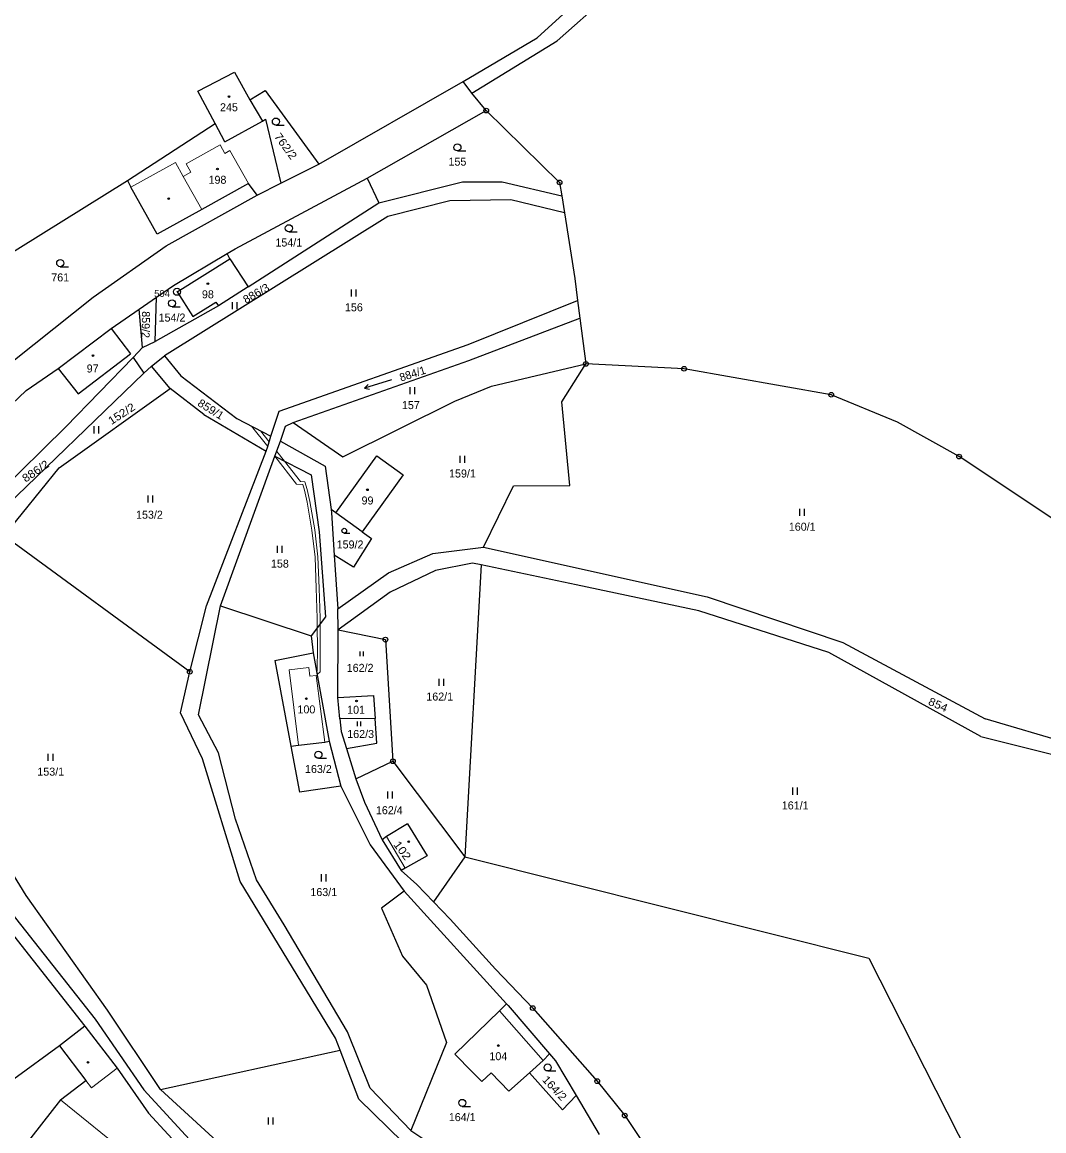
# Model space of a CAD drawing. Extents: x -739410 to -735662, y -942282 to -940043.
# Drawn here: x -737671 to -737454.1, y -940728 to -940492.6 of the extents above; entities that cross this region are included whole.
import ezdxf
from ezdxf.enums import TextEntityAlignment as Align

# ---------------------------------------------------------------- set-up
doc = ezdxf.new("R2010")
doc.units = 0
doc.header["$LTSCALE"] = 0.68
for name, color, linetype, lineweight in [('1', 7, 'Continuous', 25), ('13', 7, 'Continuous', 13), ('3', 7, 'Continuous', 25), ('4', 7, 'Continuous', 13), ('5', 7, 'Continuous', 25), ('8', 7, 'Continuous', 25)]:
    doc.layers.add(name, color=color, linetype=linetype, lineweight=lineweight)
doc.layers.add('2', color=7, linetype='Continuous')

msp = doc.modelspace()

# ---------------------------------------------------------------- linework, layer by layer
at = {"layer": '1'}
for p, q in [((-737561.67, -940495.92), (-737548.71, -940484.07)), ((-737557.45, -940496.56), (-737545.62, -940486.1)), ((-737577.41, -940505.16), (-737561.67, -940495.92)), ((-737575.54, -940507.67), (-737557.45, -940496.56)), ((-737633.69, -940507.25), (-737625.96, -940503.21)), ((-737625.96, -940503.21), (-737622.67, -940509.06)), ((-737608.04, -940522.72), (-737577.41, -940505.16)), ((-737575.54, -940507.67), (-737577.41, -940505.16)), ((-737630.02, -940514.12), (-737633.69, -940507.25)), ((-737622.67, -940509.06), (-737619.45, -940507.08)), ((-737619.45, -940507.08), (-737608.04, -940522.72)), ((-737572.48, -940511.35), (-737575.54, -940507.67)), ((-737622.67, -940509.06), (-737619.97, -940513.57)), ((-737597.76, -940525.71), (-737572.48, -940511.35)), ((-737556.9, -940526.6), (-737572.48, -940511.35)), ((-737648.64, -940526.17), (-737630.02, -940514.12)), ((-737627.97, -940517.97), (-737630.02, -940514.12)), ((-737627.97, -940517.97), (-737619.97, -940513.57)), ((-737619.97, -940513.57), (-737619.32, -940513.15)), ((-737619.32, -940513.15), (-737616.07, -940526.8)), ((-737616.07, -940526.8), (-737608.04, -940522.72)), ((-737686.19, -940549.57), (-737648.64, -940526.17)), ((-737648.64, -940526.17), (-737647.91, -940527.59)), ((-737622.97, -940526.85), (-737632.9, -940532.37)), ((-737625.76, -940540.71), (-737597.76, -940525.71)), ((-737621.09, -940529.34), (-737622.97, -940526.85)), ((-737621.09, -940529.34), (-737616.07, -940526.8)), ((-737597.76, -940525.71), (-737595.26, -940530.94)), ((-737595.26, -940530.94), (-737577.52, -940526.46)), ((-737577.52, -940526.46), (-737569.13, -940526.46)), ((-737569.13, -940526.46), (-737556.45, -940529.45)), ((-737556.9, -940526.6), (-737556.45, -940529.45)), ((-737642.33, -940537.57), (-737647.91, -940527.59)), ((-737640.41, -940540.09), (-737621.09, -940529.34)), ((-737623.02, -940548.79), (-737595.26, -940530.94)), ((-737580.24, -940530.51), (-737593.38, -940533.82)), ((-737567.25, -940530.31), (-737580.24, -940530.51)), ((-737555.89, -940533.03), (-737567.25, -940530.31)), ((-737556.45, -940529.45), (-737555.89, -940533.03)), ((-737632.9, -940532.37), (-737642.33, -940537.57)), ((-737593.38, -940533.82), (-737640.78, -940563.44)), ((-737555.89, -940533.03), (-737553.7, -940547)), ((-737655.92, -940550.97), (-737640.41, -940540.09)), ((-737627.47, -940541.72), (-737625.76, -940540.71)), ((-737638.91, -940548.51), (-737627.47, -940541.72)), ((-737638.12, -940549.83), (-737626.91, -940542.82)), ((-737626.91, -940542.82), (-737627.47, -940541.72)), ((-737626.91, -940542.82), (-737623.02, -940548.79)), ((-737553.7, -940547), (-737553.08, -940551.7)), ((-737642.46, -940550.97), (-737638.91, -940548.51)), ((-737638.12, -940549.83), (-737634.81, -940555.08)), ((-737623.02, -940548.79), (-737629.35, -940552.84)), ((-737672.65, -940564.31), (-737655.92, -940550.97)), ((-737646.16, -940553.54), (-737642.46, -940550.97)), ((-737642.79, -940560.38), (-737642.46, -940550.97)), ((-737629.35, -940552.84), (-737642.79, -940560.38)), ((-737634.81, -940555.08), (-737629.89, -940552.01)), ((-737629.89, -940552.01), (-737629.35, -940552.84)), ((-737576.32, -940561.02), (-737553.08, -940551.7)), ((-737553.08, -940551.7), (-737552.59, -940555.42)), ((-737652.11, -940557.66), (-737646.16, -940553.54)), ((-737645.46, -940561.66), (-737646.16, -940553.54)), ((-737576.17, -940564.43), (-737552.59, -940555.42)), ((-737552.59, -940555.42), (-737551.3, -940565.14)), ((-737663.34, -940566.12), (-737652.11, -940557.66)), ((-737652.11, -940557.66), (-737648, -940563.03)), ((-737647.45, -940563.79), (-737645.46, -940561.66)), ((-737645.46, -940561.66), (-737642.79, -940560.38)), ((-737616.45, -940575.19), (-737576.32, -940561.02)), ((-737661.75, -940578.53), (-737647.45, -940563.79)), ((-737659.16, -940571.5), (-737648, -940563.03)), ((-737647.45, -940563.79), (-737645.19, -940567.1)), ((-737643.53, -940565.59), (-737640.78, -940563.44)), ((-737640.78, -940563.44), (-737637.36, -940567.7)), ((-737613.5, -940577.58), (-737576.17, -940564.43)), ((-737670.2, -940570.81), (-737663.34, -940566.12)), ((-737663.34, -940566.12), (-737659.16, -940571.5)), ((-737643.53, -940565.59), (-737645.19, -940567.1)), ((-737639.58, -940570.36), (-737643.53, -940565.59)), ((-737571.36, -940569.87), (-737551.3, -940565.14)), ((-737556.45, -940573.22), (-737551.3, -940565.14)), ((-737530.47, -940566.17), (-737551.3, -940565.14)), ((-737499.22, -940571.7), (-737530.47, -940566.17)), ((-737645.19, -940567.1), (-737678.21, -940598.98)), ((-737637.36, -940567.7), (-737625.45, -940576.74)), ((-737689.83, -940589.57), (-737670.2, -940570.81)), ((-737663.18, -940587.21), (-737639.58, -940570.36)), ((-737632.47, -940575.86), (-737639.58, -940570.36)), ((-737579.18, -940573.03), (-737571.36, -940569.87)), ((-737485.14, -940577.53), (-737499.22, -940571.7)), ((-737602.91, -940584.85), (-737579.18, -940573.03)), ((-737554.76, -940590.93), (-737556.45, -940573.22)), ((-737632.47, -940575.86), (-737619.22, -940583.69)), ((-737618.23, -940580.49), (-737616.45, -940575.19)), ((-737679.94, -940596.35), (-737661.75, -940578.53)), ((-737625.45, -940576.74), (-737618.23, -940580.49)), ((-737616.16, -940581.55), (-737615.1, -940578.35)), ((-737615.1, -940578.35), (-737613.5, -940577.58)), ((-737613.5, -940577.58), (-737602.91, -940584.85)), ((-737472.09, -940584.82), (-737485.14, -940577.53)), ((-737618.83, -940582.69), (-737618.23, -940580.49)), ((-737619.22, -940583.69), (-737618.83, -940582.69)), ((-737617.35, -940584.76), (-737616.16, -940581.55)), ((-737616.16, -940581.55), (-737606.67, -940586.85)), ((-737631.88, -940616.55), (-737619.22, -940583.69)), ((-737628.92, -940616.53), (-737617.35, -940584.76)), ((-737617.35, -940584.76), (-737609.62, -940588.73)), ((-737604.42, -940596.8), (-737595.72, -940584.68)), ((-737595.72, -940584.68), (-737590.11, -940588.71)), ((-737454.28, -940596.64), (-737472.09, -940584.82)), ((-737674.87, -940601.62), (-737663.18, -940587.21)), ((-737606.67, -940586.85), (-737605.42, -940596.03)), ((-737609.62, -940588.73), (-737607.99, -940600.78)), ((-737590.11, -940588.71), (-737598.8, -940600.79)), ((-737573.07, -940604.08), (-737566.69, -940591)), ((-737566.69, -940591), (-737554.76, -940590.93)), ((-737604.42, -940596.8), (-737605.42, -940596.03)), ((-737605.42, -940596.03), (-737605.32, -940596.76)), ((-737605.32, -940596.76), (-737604.76, -940605.77)), ((-737598.8, -940600.79), (-737604.42, -940596.8)), ((-737433.14, -940611.23), (-737454.28, -940596.64)), ((-737635.43, -940630.52), (-737674.87, -940601.62)), ((-737607.99, -940600.78), (-737606.64, -940618.85)), ((-737596.81, -940602.23), (-737600.68, -940608.28)), ((-737598.8, -940600.79), (-737596.81, -940602.23)), ((-737583.79, -940605.43), (-737573.07, -940604.08)), ((-737573.07, -940604.08), (-737525.58, -940614.62)), ((-737604.76, -940605.77), (-737604, -940617.14)), ((-737600.68, -940608.28), (-737604.76, -940605.77)), ((-737593.2, -940609.54), (-737583.79, -940605.43)), ((-737583.22, -940609.03), (-737592.89, -940613.59)), ((-737575.39, -940607.43), (-737583.22, -940609.03)), ((-737573.54, -940607.82), (-737577.04, -940669.84)), ((-737573.54, -940607.82), (-737575.39, -940607.43)), ((-737553.37, -940612.07), (-737573.54, -940607.82)), ((-737604, -940617.14), (-737593.2, -940609.54)), ((-737592.89, -940613.59), (-737603.92, -940621.58)), ((-737527.36, -940617.57), (-737553.37, -940612.07)), ((-737525.58, -940614.62), (-737496.8, -940624.3)), ((-737635.43, -940630.52), (-737631.88, -940616.55)), ((-737633.58, -940639.69), (-737628.92, -940616.53)), ((-737628.92, -940616.53), (-737609.62, -940622.86)), ((-737603.92, -940621.58), (-737604, -940617.14)), ((-737499.75, -940626.43), (-737527.36, -940617.57)), ((-737606.64, -940618.85), (-737609.62, -940622.86)), ((-737609.62, -940622.86), (-737609.26, -940626.5)), ((-737603.97, -940636), (-737603.92, -940621.58)), ((-737496.8, -940624.3), (-737466.56, -940640.53)), ((-737617.38, -940628.15), (-737609.26, -940626.5)), ((-737617.38, -940628.15), (-737613.98, -940646.3)), ((-737609.26, -940626.5), (-737605.83, -940645.25)), ((-737467.44, -940644.28), (-737499.75, -940626.43)), ((-737637.39, -940639.21), (-737635.43, -940630.52)), ((-737603.97, -940636), (-737596.42, -940635.57)), ((-737603.57, -940640.5), (-737603.97, -940636)), ((-737596.42, -940635.57), (-737596.08, -940640.47)), ((-737632.75, -940648.98), (-737637.39, -940639.21)), ((-737629.36, -940647.71), (-737633.58, -940639.69)), ((-737596.08, -940640.47), (-737603.57, -940640.5)), ((-737603.57, -940640.5), (-737603.27, -940643.21)), ((-737595.72, -940645.65), (-737596.08, -940640.47)), ((-737443.31, -940647.36), (-737466.56, -940640.53)), ((-737603.27, -940643.21), (-737602.15, -940646.84)), ((-737467.44, -940644.28), (-737443.67, -940650.24)), ((-737613.98, -940646.3), (-737612.33, -940646.11)), ((-737613.98, -940646.3), (-737612.15, -940656.05)), ((-737612.33, -940646.11), (-737606.78, -940645.48)), ((-737606.78, -940645.48), (-737605.83, -940645.25)), ((-737605.83, -940645.25), (-737603.38, -940654.8)), ((-737602.15, -940646.84), (-737595.72, -940645.65)), ((-737602.15, -940646.84), (-737600.17, -940653.26)), ((-737624.76, -940675.02), (-737632.75, -940648.98)), ((-737625.72, -940661.85), (-737629.36, -940647.71)), ((-737600.17, -940653.26), (-737592.31, -940649.52)), ((-737592.31, -940649.52), (-737577.04, -940669.84)), ((-737600.17, -940653.26), (-737598.34, -940658.21)), ((-737603.38, -940654.8), (-737612.15, -940656.05)), ((-737603.38, -940654.8), (-737597.15, -940667.24)), ((-737598.34, -940658.21), (-737594.55, -940666.21)), ((-737621.29, -940674.68), (-737625.72, -940661.85)), ((-737589.21, -940662.8), (-737593.69, -940665.5)), ((-737589.21, -940662.8), (-737585.03, -940669.61)), ((-737593.69, -940665.5), (-737594.55, -940666.21)), ((-737597.15, -940667.24), (-737589.92, -940677.1)), ((-737594.55, -940666.21), (-737590.52, -940672.7)), ((-737585.03, -940669.61), (-737589.7, -940672.2)), ((-737577.04, -940669.84), (-737583.68, -940679.39)), ((-737577.04, -940669.84), (-737491.24, -940691.36)), ((-737670.19, -940678.03), (-737673.45, -940672.74)), ((-737589.7, -940672.2), (-737590.52, -940672.7)), ((-737590.52, -940672.7), (-737587.19, -940675.7)), ((-737604.47, -940708.35), (-737624.76, -940675.02)), ((-737615.38, -940684.27), (-737621.29, -940674.68)), ((-737589.92, -940677.1), (-737594.74, -940680.7)), ((-737589.92, -940677.1), (-737568.17, -940701)), ((-737583.68, -940679.39), (-737587.19, -940675.7)), ((-737675.36, -940679.19), (-737655.5, -940704.3)), ((-737652.91, -940702.38), (-737670.19, -940678.03)), ((-737580.17, -940683.07), (-737583.68, -940679.39)), ((-737677.9, -940680.14), (-737657.7, -940705.77)), ((-737594.74, -940680.7), (-737590.29, -940690.89)), ((-737601.91, -940707), (-737615.38, -940684.27)), ((-737570.54, -940693.7), (-737580.17, -940683.07)), ((-737590.29, -940690.89), (-737585.19, -940697.05)), ((-737491.24, -940691.36), (-737469.27, -940734.66)), ((-737585.19, -940697.05), (-737580.95, -940709.26)), ((-737569.67, -940702.48), (-737568.17, -940701)), ((-737568.17, -940701), (-737567.84, -940701.36)), ((-737641.62, -940719.25), (-737652.91, -940702.38)), ((-737579.15, -940711.7), (-737569.67, -940702.48)), ((-737567.84, -940701.36), (-737559.02, -940711.67)), ((-737657.7, -940705.77), (-737663.12, -940709.92)), ((-737657.7, -940705.77), (-737650.88, -940714.72)), ((-737655.5, -940704.3), (-737645.16, -940719.26)), ((-737597.12, -940718.97), (-737601.91, -940707)), ((-737663.12, -940709.92), (-737672.8, -940717.05)), ((-737663.12, -940709.92), (-737657.5, -940717.29)), ((-737603.5, -940710.89), (-737604.47, -940708.35)), ((-737580.95, -940709.26), (-737588.49, -940727.93)), ((-737641.62, -940719.25), (-737603.5, -940710.89)), ((-737599.52, -940721.29), (-737603.5, -940710.89)), ((-737579.15, -940711.7), (-737575.45, -940715.44)), ((-737560.42, -940713.09), (-737559.02, -940711.67)), ((-737559.02, -940711.67), (-737557.78, -940713.12)), ((-737650.88, -940714.72), (-737644.16, -940724.23)), ((-737560.42, -940713.09), (-737563.33, -940715.67)), ((-737557.78, -940713.12), (-737553.41, -940720.47)), ((-737662.89, -940721.44), (-737657.5, -940717.29)), ((-737575.45, -940715.44), (-737573.44, -940717.49)), ((-737573.44, -940717.49), (-737571.42, -940715.67)), ((-737567.69, -940719.55), (-737571.42, -940715.67)), ((-737563.33, -940715.67), (-737567.69, -940719.55)), ((-737563.33, -940715.67), (-737556.28, -940723.51)), ((-737645.16, -940719.26), (-737624.21, -940742.12)), ((-737625.71, -940733.81), (-737641.62, -940719.25)), ((-737597.12, -940718.97), (-737588.49, -940727.93)), ((-737662.89, -940721.44), (-737670.96, -940731.75)), ((-737590.17, -940730.4), (-737599.52, -940721.29)), ((-737556.28, -940723.51), (-737553.41, -940720.47)), ((-737553.41, -940720.47), (-737548.49, -940728.76)), ((-737644.16, -940724.23), (-737626.97, -940742.91)), ((-737588.49, -940727.93), (-737578.82, -940734.32))]:
    msp.add_line(p, q, dxfattribs=at)
for points in [[(-737603.92, -940621.58), (-737593.88, -940623.7), (-737592.31, -940649.52)], [(-737570.54, -940693.7), (-737562.59, -940701.93), (-737548.92, -940717.45), (-737543.06, -940724.76), (-737530.41, -940743.73), (-737525.52, -940751.74), (-737521.4, -940760.57), (-737512.35, -940780.93)]]:
    msp.add_lwpolyline(points, dxfattribs=at)
at = {"layer": '13'}
for points in [[(-737622.34, -940578.35), (-737618.83, -940582.69), (-737618.56, -940581.69), (-737620.39, -940579.37)], [(-737608.53, -940630.49), (-737608.41, -940631.12), (-737607.76, -940630.56), (-737607.72, -940625.25), (-737607.76, -940620.36), (-737607.77, -940619.12), (-737607.96, -940612.74), (-737608.21, -940606.11), (-737608.89, -940600.4), (-737609.93, -940594.38), (-737610.47, -940591.78), (-737610.99, -940590.19), (-737611.91, -940590.14), (-737615.32, -940585.8), (-737616.96, -940583.72), (-737617.35, -940584.76), (-737612.74, -940590.7), (-737611.43, -940590.77), (-737611.05, -940591.93), (-737610.52, -940594.49), (-737609.48, -940600.48), (-737608.81, -940606.16), (-737608.56, -940612.76), (-737608.37, -940619.14), (-737608.36, -940621.16), (-737608.32, -940625.25), (-737608.36, -940630.32)]]:
    msp.add_lwpolyline(points, close=True, dxfattribs=at)
at = {"layer": '3'}
for p, q in [((-737617.143, -940514.43), (-737615.393, -940514.43)), ((-737578.593, -940519.92), (-737576.843, -940519.92)), ((-737614.393, -940537.09), (-737612.643, -940537.09)), ((-737662.933, -940544.5), (-737661.183, -940544.5)), ((-737601.091, -940550.85), (-737601.091, -940549.35)), ((-737600.09, -940550.85), (-737600.09, -940549.35)), ((-737626.361, -940553.53), (-737626.361, -940552.03)), ((-737625.36, -940553.53), (-737625.36, -940552.03)), ((-737639.193, -940553.03), (-737637.443, -940553.03)), ((-737598.348, -940570.294), (-737597.56, -940569.529)), ((-737588.661, -940571.55), (-737588.661, -940570.05)), ((-737587.66, -940571.55), (-737587.66, -940570.05)), ((-737655.731, -940579.89), (-737655.731, -940578.39)), ((-737654.73, -940579.89), (-737654.73, -940578.39)), ((-737578.041, -940586.14), (-737578.041, -940584.64)), ((-737577.04, -940586.14), (-737577.04, -940584.64)), ((-737644.261, -940594.56), (-737644.261, -940593.06)), ((-737643.26, -940594.56), (-737643.26, -940593.06)), ((-737505.901, -940597.44), (-737505.901, -940595.94)), ((-737504.9, -940597.44), (-737504.9, -940595.94)), ((-737602.625, -940601.06), (-737601.453, -940601.06)), ((-737616.801, -940605.28), (-737616.801, -940603.78)), ((-737615.8, -940605.28), (-737615.8, -940603.78)), ((-737599.242, -940627.22), (-737599.242, -940626.215)), ((-737598.572, -940627.22), (-737598.572, -940626.215)), ((-737582.491, -940633.51), (-737582.491, -940632.01)), ((-737581.49, -940633.51), (-737581.49, -940632.01)), ((-737599.812, -940642.08), (-737599.812, -940641.075)), ((-737599.142, -940642.08), (-737599.142, -940641.075)), ((-737665.461, -940649.45), (-737665.461, -940647.95)), ((-737664.46, -940649.45), (-737664.46, -940647.95)), ((-737608.113, -940648.89), (-737606.363, -940648.89)), ((-737593.351, -940657.45), (-737593.351, -940655.95)), ((-737592.35, -940657.45), (-737592.35, -940655.95)), ((-737507.391, -940656.62), (-737507.391, -940655.12)), ((-737506.39, -940656.62), (-737506.39, -940655.12)), ((-737607.491, -940675.02), (-737607.491, -940673.52)), ((-737606.49, -940675.02), (-737606.49, -940673.52)), ((-737559.433, -940715.28), (-737557.683, -940715.28)), ((-737577.573, -940722.81), (-737575.823, -940722.81)), ((-737618.731, -940726.66), (-737618.731, -940725.16)), ((-737617.73, -940726.66), (-737617.73, -940725.16))]:
    msp.add_line(p, q, dxfattribs=at)
msp.add_lwpolyline([(-737592.61, -940568.54), (-737598.348, -940570.294), (-737597.267, -940570.488)], dxfattribs=at)
for centre, radius in [((-737617.1429, -940513.6798), 0.75), ((-737578.5929, -940519.1698), 0.75), ((-737614.3929, -940536.3398), 0.75), ((-737662.9329, -940543.7498), 0.75), ((-737639.1929, -940552.2798), 0.75), ((-737602.6252, -940600.5574), 0.5025), ((-737608.1129, -940648.1398), 0.75), ((-737559.4329, -940714.5298), 0.75), ((-737577.5729, -940722.0598), 0.75)]:
    msp.add_circle(centre, radius, dxfattribs=at)
at = {"layer": '4'}
for p, q in [((-737628.98, -940518.64), (-737636.22, -940522.65)), ((-737622.97, -940526.85), (-737626.89, -940519.85)), ((-737638.48, -940522.39), (-737647.91, -940527.59)), ((-737636.82, -940525.35), (-737638.48, -940522.39)), ((-737635.21, -940524.46), (-737636.82, -940525.35)), ((-737635.21, -940524.46), (-737636.22, -940522.65)), ((-737632.9, -940532.37), (-737636.82, -940525.35)), ((-737610.17, -940629.6), (-737614.36, -940630.12)), ((-737614.36, -940630.12), (-737612.33, -940646.11)), ((-737609.93, -940631.45), (-737610.17, -940629.6)), ((-737608.61, -940631.29), (-737609.93, -940631.45)), ((-737606.78, -940645.48), (-737608.61, -940631.29)), ((-737593.69, -940665.5), (-737589.7, -940672.2)), ((-737569.67, -940702.48), (-737560.42, -940713.09)), ((-737650.88, -940714.72), (-737656.3, -940718.87)), ((-737657.5, -940717.29), (-737656.3, -940718.87)), ((-737662.89, -940721.44), (-737647.02, -940734.23))]:
    msp.add_line(p, q, dxfattribs=at)
msp.add_lwpolyline([(-737626.89, -940519.85), (-737627.97, -940520.45), (-737628.98, -940518.64)], dxfattribs=at)
at = {"layer": '5'}
for centre in [(-737627.1168, -940508.3692), (-737629.5568, -940523.7692), (-737639.8968, -940530.0492), (-737631.5868, -940548.0892), (-737655.9668, -940563.3692), (-737597.6968, -940591.8692), (-737610.6768, -940636.2292), (-737600.0168, -940636.7092), (-737588.9468, -940666.6092), (-737569.9168, -940709.8792), (-737657.0268, -940713.4592)]:
    msp.add_circle(centre, 0.175, dxfattribs=at)
at = {"layer": '8'}
for centre, radius in [((-737572.48, -940511.3499), 0.5), ((-737572.48, -940511.3499), 0.0303), ((-737556.9, -940526.5999), 0.5), ((-737556.9, -940526.5999), 0.0303), ((-737638.14, -940549.8298), 0.75), ((-737638.14, -940549.8298), 0.03), ((-737551.3, -940565.1399), 0.5), ((-737551.3, -940565.1399), 0.0303), ((-737530.47, -940566.1699), 0.5), ((-737530.47, -940566.1699), 0.0303), ((-737499.22, -940571.6999), 0.5), ((-737499.22, -940571.6999), 0.0303), ((-737472.09, -940584.8199), 0.5), ((-737472.09, -940584.8199), 0.0303), ((-737593.88, -940623.6999), 0.5), ((-737593.88, -940623.6999), 0.0303), ((-737635.43, -940630.5199), 0.5), ((-737635.43, -940630.5199), 0.0303), ((-737592.31, -940649.5199), 0.5), ((-737592.31, -940649.5199), 0.0303), ((-737562.59, -940701.9299), 0.5), ((-737562.59, -940701.9299), 0.0303), ((-737548.92, -940717.4499), 0.5), ((-737548.92, -940717.4499), 0.0303), ((-737543.06, -940724.7599), 0.5), ((-737543.06, -940724.7599), 0.0303)]:
    msp.add_circle(centre, radius, dxfattribs=at)

# ---------------------------------------------------------------- texts
at = {"layer": '2'}
for s, p in [('245', (-737627.109, -940511.495)), ('155', (-737578.599, -940523.045)), ('198', (-737629.549, -940526.895)), ('154/1', (-737614.4, -940540.215)), ('761', (-737662.939, -940547.625)), ('98', (-737631.579, -940551.215)), ('156', (-737600.579, -940553.975)), ('154/2', (-737639.2, -940556.155)), ('97', (-737656.049, -940566.965)), ('157', (-737588.489, -940574.745)), ('159/1', (-737577.53, -940589.265)), ('99', (-737597.689, -940594.995)), ('153/2', (-737643.99, -940598.015)), ('160/1', (-737505.39, -940600.565)), ('159/2', (-737601.39, -940604.335)), ('158', (-737616.289, -940608.405)), ('162/2', (-737599.26, -940630.535)), ('162/1', (-737582.36, -940636.635)), ('100', (-737610.669, -940639.355)), ('101', (-737600.119, -940639.435)), ('162/3', (-737599.15, -940644.585)), ('153/1', (-737664.95, -940652.575)), ('163/2', (-737608.12, -940652.015)), ('161/1', (-737506.88, -940659.745)), ('162/4', (-737593.06, -940660.765)), ('163/1', (-737606.98, -940678.145)), ('104', (-737569.909, -940713.005)), ('164/1', (-737577.58, -940725.935))]:
    msp.add_text(s, height=1.7, dxfattribs=at).set_placement(p, align=Align.CENTER)
for s, rotation, width, p in [('762/2', 306, 1.1, (-737615.7481, -940519.4139)), ('886/3', 30, 1.05, (-737620.9205, -940550.903)), ('152/2', 33, 1.1, (-737649.4429, -940576.4434)), ('859/1', 328, 1.05, (-737631.3959, -940575.4929)), ('886/2', 34, 1.1, (-737667.6998, -940588.6189)), ('854', 336, 1.1, (-737476.8867, -940638.2864)), ('102', 307, 1.15, (-737590.9729, -940668.9855)), ('164/2', 313, 1.1, (-737558.5956, -940719.5243))]:
    msp.add_text(s, height=1.7, rotation=rotation, dxfattribs=dict(at, width=width)).set_placement(p, align=Align.CENTER)
for s, rotation, p in [('859/2', 269, (-737645.6146, -940556.7892)), ('884/1', 18, (-737587.8637, -940568.04))]:
    msp.add_text(s, height=1.7, rotation=rotation, dxfattribs=at).set_placement(p, align=Align.CENTER)
at = {"layer": '8'}
msp.add_text('504', height=1.5, dxfattribs=at).set_placement((-737639.639, -940550.947), align=Align.RIGHT)

doc.saveas('drawing.dxf')
